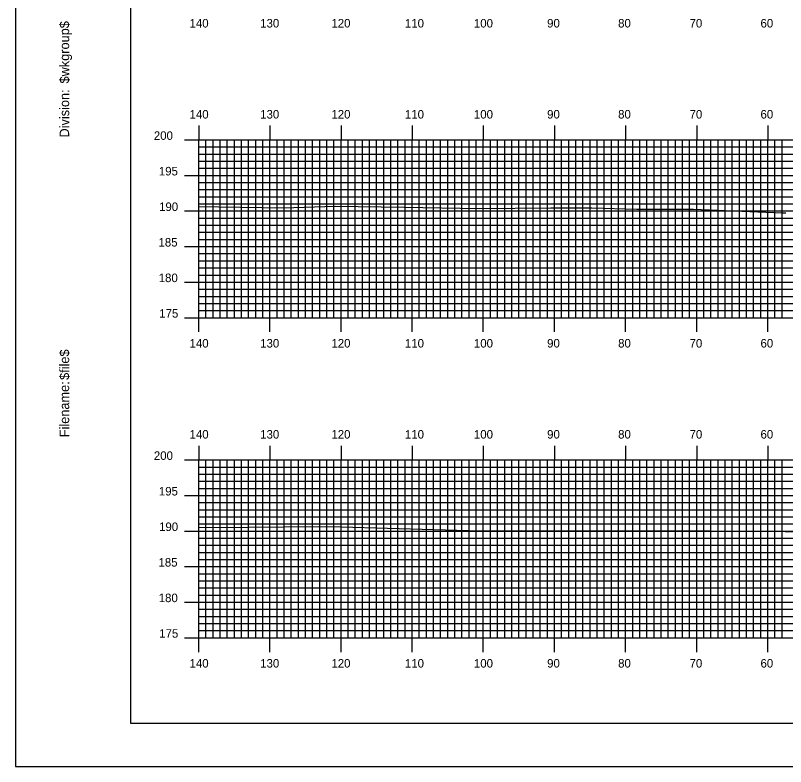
# Model space of a CAD drawing. Extents: x 1797994 to 1798337, y 442591 to 442811.
# Drawn here: x 1797994.2 to 1798102.5, y 442590.5 to 442696.2 of the extents above; entities that cross this region are included whole.
import ezdxf

# ---------------------------------------------------------------- set-up
doc = ezdxf.new("R2010")
doc.units = 0
for name, color, linetype in [('BORDER', 7, 'Continuous'), ('H_V ANNOTATION', 7, 'Continuous'), ('MAJOR', 7, 'Continuous'), ('MINOR', 7, 'Continuous'), ('PLOT BOUNDARY', 7, 'Continuous'), ('S_Roadway_Centerline', 7, 'Continuous')]:
    doc.layers.add(name, color=color, linetype=linetype)

msp = doc.modelspace()

# ---------------------------------------------------------------- linework, layer by layer
at = {"layer": 'BORDER'}
msp.add_lwpolyline([(1798010.36, 442596.67), (1798330.36, 442596.67), (1798330.36, 442806.67), (1798010.36, 442806.67)], close=True, dxfattribs=at)
at = {"layer": 'MAJOR'}
for p, q in [((1798019.96, 442680.67), (1798019.96, 442678.67)), ((1798029.96, 442680.67), (1798029.96, 442678.67)), ((1798039.96, 442680.67), (1798039.96, 442678.67)), ((1798049.96, 442680.67), (1798049.96, 442678.67)), ((1798059.96, 442680.67), (1798059.96, 442678.67)), ((1798069.96, 442680.67), (1798069.96, 442678.67)), ((1798079.96, 442680.67), (1798079.96, 442678.67)), ((1798089.96, 442680.67), (1798089.96, 442678.67)), ((1798099.96, 442680.67), (1798099.96, 442678.67)), ((1798017.95, 442678.67), (1798019.96, 442678.67)), ((1798019.96, 442678.67), (1798299.96, 442678.67)), ((1798019.96, 442653.67), (1798019.96, 442678.67)), ((1798019.96, 442653.67), (1798019.96, 442678.67)), ((1798019.96, 442678.67), (1798299.96, 442678.67)), ((1798029.96, 442653.67), (1798029.96, 442678.67)), ((1798039.96, 442653.67), (1798039.96, 442678.67)), ((1798049.96, 442653.67), (1798049.96, 442678.67)), ((1798059.96, 442653.67), (1798059.96, 442678.67)), ((1798069.96, 442653.67), (1798069.96, 442678.67)), ((1798079.96, 442653.67), (1798079.96, 442678.67)), ((1798089.96, 442653.67), (1798089.96, 442678.67)), ((1798099.96, 442653.67), (1798099.96, 442678.67)), ((1798017.95, 442673.67), (1798019.96, 442673.67)), ((1798019.96, 442673.67), (1798299.96, 442673.67)), ((1798017.95, 442668.67), (1798019.96, 442668.67)), ((1798019.96, 442668.67), (1798299.96, 442668.67)), ((1798017.95, 442663.67), (1798019.96, 442663.67)), ((1798019.96, 442663.67), (1798299.96, 442663.67)), ((1798017.95, 442658.67), (1798019.96, 442658.67)), ((1798019.96, 442658.67), (1798299.96, 442658.67)), ((1798017.95, 442653.67), (1798019.96, 442653.67)), ((1798019.96, 442653.67), (1798299.96, 442653.67)), ((1798019.96, 442653.67), (1798299.96, 442653.67)), ((1798019.96, 442651.66), (1798019.96, 442653.67)), ((1798029.96, 442651.66), (1798029.96, 442653.67)), ((1798039.96, 442651.66), (1798039.96, 442653.67)), ((1798049.96, 442651.66), (1798049.96, 442653.67)), ((1798059.96, 442651.66), (1798059.96, 442653.67)), ((1798069.96, 442651.66), (1798069.96, 442653.67)), ((1798079.96, 442651.66), (1798079.96, 442653.67)), ((1798089.96, 442651.66), (1798089.96, 442653.67)), ((1798099.96, 442651.66), (1798099.96, 442653.67)), ((1798019.96, 442635.67), (1798019.96, 442633.67)), ((1798029.96, 442635.67), (1798029.96, 442633.67)), ((1798039.96, 442635.67), (1798039.96, 442633.67)), ((1798049.96, 442635.67), (1798049.96, 442633.67)), ((1798059.96, 442635.67), (1798059.96, 442633.67)), ((1798069.96, 442635.67), (1798069.96, 442633.67)), ((1798079.96, 442635.67), (1798079.96, 442633.67)), ((1798089.96, 442635.67), (1798089.96, 442633.67)), ((1798099.96, 442635.67), (1798099.96, 442633.67)), ((1798017.95, 442633.67), (1798019.96, 442633.67)), ((1798019.96, 442633.67), (1798299.96, 442633.67)), ((1798019.96, 442608.67), (1798019.96, 442633.67)), ((1798019.96, 442608.67), (1798019.96, 442633.67)), ((1798019.96, 442633.67), (1798299.96, 442633.67)), ((1798029.96, 442608.67), (1798029.96, 442633.67)), ((1798039.96, 442608.67), (1798039.96, 442633.67)), ((1798049.96, 442608.67), (1798049.96, 442633.67)), ((1798059.96, 442608.67), (1798059.96, 442633.67)), ((1798069.96, 442608.67), (1798069.96, 442633.67)), ((1798079.96, 442608.67), (1798079.96, 442633.67)), ((1798089.96, 442608.67), (1798089.96, 442633.67)), ((1798099.96, 442608.67), (1798099.96, 442633.67)), ((1798017.95, 442628.67), (1798019.96, 442628.67)), ((1798019.96, 442628.67), (1798299.96, 442628.67)), ((1798017.95, 442623.67), (1798019.96, 442623.67)), ((1798019.96, 442623.67), (1798299.96, 442623.67)), ((1798017.95, 442618.67), (1798019.96, 442618.67)), ((1798019.96, 442618.67), (1798299.96, 442618.67)), ((1798017.95, 442613.67), (1798019.96, 442613.67)), ((1798019.96, 442613.67), (1798299.96, 442613.67)), ((1798017.95, 442608.67), (1798019.96, 442608.67)), ((1798019.96, 442608.67), (1798299.96, 442608.67)), ((1798019.96, 442608.67), (1798299.96, 442608.67)), ((1798019.96, 442606.66), (1798019.96, 442608.67)), ((1798029.96, 442606.66), (1798029.96, 442608.67)), ((1798039.96, 442606.66), (1798039.96, 442608.67)), ((1798049.96, 442606.66), (1798049.96, 442608.67)), ((1798059.96, 442606.66), (1798059.96, 442608.67)), ((1798069.96, 442606.66), (1798069.96, 442608.67)), ((1798079.96, 442606.66), (1798079.96, 442608.67)), ((1798089.96, 442606.66), (1798089.96, 442608.67)), ((1798099.96, 442606.66), (1798099.96, 442608.67))]:
    msp.add_line(p, q, dxfattribs=at)
at = {"layer": 'MINOR'}
for p, q in [((1798020.96, 442653.67), (1798020.96, 442678.67)), ((1798021.96, 442653.67), (1798021.96, 442678.67)), ((1798022.96, 442653.67), (1798022.96, 442678.67)), ((1798023.96, 442653.67), (1798023.96, 442678.67)), ((1798024.96, 442653.67), (1798024.96, 442678.67)), ((1798025.96, 442653.67), (1798025.96, 442678.67)), ((1798026.96, 442653.67), (1798026.96, 442678.67)), ((1798027.96, 442653.67), (1798027.96, 442678.67)), ((1798028.96, 442653.67), (1798028.96, 442678.67)), ((1798030.96, 442653.67), (1798030.96, 442678.67)), ((1798031.96, 442653.67), (1798031.96, 442678.67)), ((1798032.96, 442653.67), (1798032.96, 442678.67)), ((1798033.96, 442653.67), (1798033.96, 442678.67)), ((1798034.96, 442653.67), (1798034.96, 442678.67)), ((1798035.96, 442653.67), (1798035.96, 442678.67)), ((1798036.96, 442653.67), (1798036.96, 442678.67)), ((1798037.96, 442653.67), (1798037.96, 442678.67)), ((1798038.96, 442653.67), (1798038.96, 442678.67)), ((1798040.96, 442653.67), (1798040.96, 442678.67)), ((1798041.96, 442653.67), (1798041.96, 442678.67)), ((1798042.96, 442653.67), (1798042.96, 442678.67)), ((1798043.96, 442653.67), (1798043.96, 442678.67)), ((1798044.96, 442653.67), (1798044.96, 442678.67)), ((1798045.96, 442653.67), (1798045.96, 442678.67)), ((1798046.96, 442653.67), (1798046.96, 442678.67)), ((1798047.96, 442653.67), (1798047.96, 442678.67)), ((1798048.96, 442653.67), (1798048.96, 442678.67)), ((1798050.96, 442653.67), (1798050.96, 442678.67)), ((1798051.96, 442653.67), (1798051.96, 442678.67)), ((1798052.96, 442653.67), (1798052.96, 442678.67)), ((1798053.96, 442653.67), (1798053.96, 442678.67)), ((1798054.96, 442653.67), (1798054.96, 442678.67)), ((1798055.96, 442653.67), (1798055.96, 442678.67)), ((1798056.96, 442653.67), (1798056.96, 442678.67)), ((1798057.96, 442653.67), (1798057.96, 442678.67)), ((1798058.96, 442653.67), (1798058.96, 442678.67)), ((1798060.96, 442653.67), (1798060.96, 442678.67)), ((1798061.96, 442653.67), (1798061.96, 442678.67)), ((1798062.96, 442653.67), (1798062.96, 442678.67)), ((1798063.96, 442653.67), (1798063.96, 442678.67)), ((1798064.96, 442653.67), (1798064.96, 442678.67)), ((1798065.96, 442653.67), (1798065.96, 442678.67)), ((1798066.96, 442653.67), (1798066.96, 442678.67)), ((1798067.96, 442653.67), (1798067.96, 442678.67)), ((1798068.96, 442653.67), (1798068.96, 442678.67)), ((1798070.96, 442653.67), (1798070.96, 442678.67)), ((1798071.96, 442653.67), (1798071.96, 442678.67)), ((1798072.96, 442653.67), (1798072.96, 442678.67)), ((1798073.96, 442653.67), (1798073.96, 442678.67)), ((1798074.96, 442653.67), (1798074.96, 442678.67)), ((1798075.96, 442653.67), (1798075.96, 442678.67)), ((1798076.96, 442653.67), (1798076.96, 442678.67)), ((1798077.96, 442653.67), (1798077.96, 442678.67)), ((1798078.96, 442653.67), (1798078.96, 442678.67)), ((1798080.96, 442653.67), (1798080.96, 442678.67)), ((1798081.96, 442653.67), (1798081.96, 442678.67)), ((1798082.96, 442653.67), (1798082.96, 442678.67)), ((1798083.96, 442653.67), (1798083.96, 442678.67)), ((1798084.96, 442653.67), (1798084.96, 442678.67)), ((1798085.96, 442653.67), (1798085.96, 442678.67)), ((1798086.96, 442653.67), (1798086.96, 442678.67)), ((1798087.96, 442653.67), (1798087.96, 442678.67)), ((1798088.96, 442653.67), (1798088.96, 442678.67)), ((1798090.96, 442653.67), (1798090.96, 442678.67)), ((1798091.96, 442653.67), (1798091.96, 442678.67)), ((1798092.96, 442653.67), (1798092.96, 442678.67)), ((1798093.96, 442653.67), (1798093.96, 442678.67)), ((1798094.96, 442653.67), (1798094.96, 442678.67)), ((1798095.96, 442653.67), (1798095.96, 442678.67)), ((1798096.96, 442653.67), (1798096.96, 442678.67)), ((1798097.96, 442653.67), (1798097.96, 442678.67)), ((1798098.96, 442653.67), (1798098.96, 442678.67)), ((1798100.96, 442653.67), (1798100.96, 442678.67)), ((1798101.96, 442653.67), (1798101.96, 442678.67)), ((1798019.96, 442677.67), (1798299.96, 442677.67)), ((1798019.96, 442677.67), (1798021.96, 442677.67)), ((1798019.96, 442676.67), (1798299.96, 442676.67)), ((1798019.96, 442676.67), (1798021.96, 442676.67)), ((1798019.96, 442675.67), (1798299.96, 442675.67)), ((1798019.96, 442675.67), (1798021.96, 442675.67)), ((1798019.96, 442674.67), (1798299.96, 442674.67)), ((1798019.96, 442674.67), (1798021.96, 442674.67)), ((1798019.96, 442672.67), (1798299.96, 442672.67)), ((1798019.96, 442672.67), (1798021.96, 442672.67)), ((1798019.96, 442671.67), (1798299.96, 442671.67)), ((1798019.96, 442671.67), (1798021.96, 442671.67)), ((1798019.96, 442670.67), (1798299.96, 442670.67)), ((1798019.96, 442670.67), (1798021.96, 442670.67)), ((1798019.96, 442669.67), (1798299.96, 442669.67)), ((1798019.96, 442669.67), (1798021.96, 442669.67)), ((1798019.96, 442667.67), (1798299.96, 442667.67)), ((1798019.96, 442667.67), (1798021.96, 442667.67)), ((1798019.96, 442666.67), (1798299.96, 442666.67)), ((1798019.96, 442666.67), (1798021.96, 442666.67)), ((1798019.96, 442665.67), (1798299.96, 442665.67)), ((1798019.96, 442665.67), (1798021.96, 442665.67)), ((1798019.96, 442664.67), (1798299.96, 442664.67)), ((1798019.96, 442664.67), (1798021.96, 442664.67)), ((1798019.96, 442662.67), (1798299.96, 442662.67)), ((1798019.96, 442662.67), (1798021.96, 442662.67)), ((1798019.96, 442661.67), (1798299.96, 442661.67)), ((1798019.96, 442661.67), (1798021.96, 442661.67)), ((1798019.96, 442660.67), (1798299.96, 442660.67)), ((1798019.96, 442660.67), (1798021.96, 442660.67)), ((1798019.96, 442659.67), (1798299.96, 442659.67)), ((1798019.96, 442659.67), (1798021.96, 442659.67)), ((1798019.96, 442657.67), (1798299.96, 442657.67)), ((1798019.96, 442657.67), (1798021.96, 442657.67)), ((1798019.96, 442656.67), (1798299.96, 442656.67)), ((1798019.96, 442656.67), (1798021.96, 442656.67)), ((1798019.96, 442655.67), (1798299.96, 442655.67)), ((1798019.96, 442655.67), (1798021.96, 442655.67)), ((1798019.96, 442654.67), (1798299.96, 442654.67)), ((1798019.96, 442654.67), (1798021.96, 442654.67)), ((1798020.96, 442608.67), (1798020.96, 442633.67)), ((1798021.96, 442608.67), (1798021.96, 442633.67)), ((1798022.96, 442608.67), (1798022.96, 442633.67)), ((1798023.96, 442608.67), (1798023.96, 442633.67)), ((1798024.96, 442608.67), (1798024.96, 442633.67)), ((1798025.96, 442608.67), (1798025.96, 442633.67)), ((1798026.96, 442608.67), (1798026.96, 442633.67)), ((1798027.96, 442608.67), (1798027.96, 442633.67)), ((1798028.96, 442608.67), (1798028.96, 442633.67)), ((1798030.96, 442608.67), (1798030.96, 442633.67)), ((1798031.96, 442608.67), (1798031.96, 442633.67)), ((1798032.96, 442608.67), (1798032.96, 442633.67)), ((1798033.96, 442608.67), (1798033.96, 442633.67)), ((1798034.96, 442608.67), (1798034.96, 442633.67)), ((1798035.96, 442608.67), (1798035.96, 442633.67)), ((1798036.96, 442608.67), (1798036.96, 442633.67)), ((1798037.96, 442608.67), (1798037.96, 442633.67)), ((1798038.96, 442608.67), (1798038.96, 442633.67)), ((1798040.96, 442608.67), (1798040.96, 442633.67)), ((1798041.96, 442608.67), (1798041.96, 442633.67)), ((1798042.96, 442608.67), (1798042.96, 442633.67)), ((1798043.96, 442608.67), (1798043.96, 442633.67)), ((1798044.96, 442608.67), (1798044.96, 442633.67)), ((1798045.96, 442608.67), (1798045.96, 442633.67)), ((1798046.96, 442608.67), (1798046.96, 442633.67)), ((1798047.96, 442608.67), (1798047.96, 442633.67)), ((1798048.96, 442608.67), (1798048.96, 442633.67)), ((1798050.96, 442608.67), (1798050.96, 442633.67)), ((1798051.96, 442608.67), (1798051.96, 442633.67)), ((1798052.96, 442608.67), (1798052.96, 442633.67)), ((1798053.96, 442608.67), (1798053.96, 442633.67)), ((1798054.96, 442608.67), (1798054.96, 442633.67)), ((1798055.96, 442608.67), (1798055.96, 442633.67)), ((1798056.96, 442608.67), (1798056.96, 442633.67)), ((1798057.96, 442608.67), (1798057.96, 442633.67)), ((1798058.96, 442608.67), (1798058.96, 442633.67)), ((1798060.96, 442608.67), (1798060.96, 442633.67)), ((1798061.96, 442608.67), (1798061.96, 442633.67)), ((1798062.96, 442608.67), (1798062.96, 442633.67)), ((1798063.96, 442608.67), (1798063.96, 442633.67)), ((1798064.96, 442608.67), (1798064.96, 442633.67)), ((1798065.96, 442608.67), (1798065.96, 442633.67)), ((1798066.96, 442608.67), (1798066.96, 442633.67)), ((1798067.96, 442608.67), (1798067.96, 442633.67)), ((1798068.96, 442608.67), (1798068.96, 442633.67)), ((1798070.96, 442608.67), (1798070.96, 442633.67)), ((1798071.96, 442608.67), (1798071.96, 442633.67)), ((1798072.96, 442608.67), (1798072.96, 442633.67)), ((1798073.96, 442608.67), (1798073.96, 442633.67)), ((1798074.96, 442608.67), (1798074.96, 442633.67)), ((1798075.96, 442608.67), (1798075.96, 442633.67)), ((1798076.96, 442608.67), (1798076.96, 442633.67)), ((1798077.96, 442608.67), (1798077.96, 442633.67)), ((1798078.96, 442608.67), (1798078.96, 442633.67)), ((1798080.96, 442608.67), (1798080.96, 442633.67)), ((1798081.96, 442608.67), (1798081.96, 442633.67)), ((1798082.96, 442608.67), (1798082.96, 442633.67)), ((1798083.96, 442608.67), (1798083.96, 442633.67)), ((1798084.96, 442608.67), (1798084.96, 442633.67)), ((1798085.96, 442608.67), (1798085.96, 442633.67)), ((1798086.96, 442608.67), (1798086.96, 442633.67)), ((1798087.96, 442608.67), (1798087.96, 442633.67)), ((1798088.96, 442608.67), (1798088.96, 442633.67)), ((1798090.96, 442608.67), (1798090.96, 442633.67)), ((1798091.96, 442608.67), (1798091.96, 442633.67)), ((1798092.96, 442608.67), (1798092.96, 442633.67)), ((1798093.96, 442608.67), (1798093.96, 442633.67)), ((1798094.96, 442608.67), (1798094.96, 442633.67)), ((1798095.96, 442608.67), (1798095.96, 442633.67)), ((1798096.96, 442608.67), (1798096.96, 442633.67)), ((1798097.96, 442608.67), (1798097.96, 442633.67)), ((1798098.96, 442608.67), (1798098.96, 442633.67)), ((1798100.96, 442608.67), (1798100.96, 442633.67)), ((1798101.96, 442608.67), (1798101.96, 442633.67)), ((1798019.96, 442632.67), (1798299.96, 442632.67)), ((1798019.96, 442632.67), (1798021.96, 442632.67)), ((1798019.96, 442631.67), (1798299.96, 442631.67)), ((1798019.96, 442631.67), (1798021.96, 442631.67)), ((1798019.96, 442630.67), (1798299.96, 442630.67)), ((1798019.96, 442630.67), (1798021.96, 442630.67)), ((1798019.96, 442629.67), (1798299.96, 442629.67)), ((1798019.96, 442629.67), (1798021.96, 442629.67)), ((1798019.96, 442627.67), (1798299.96, 442627.67)), ((1798019.96, 442627.67), (1798021.96, 442627.67)), ((1798019.96, 442626.67), (1798299.96, 442626.67)), ((1798019.96, 442626.67), (1798021.96, 442626.67)), ((1798019.96, 442625.67), (1798299.96, 442625.67)), ((1798019.96, 442625.67), (1798021.96, 442625.67)), ((1798019.96, 442624.67), (1798299.96, 442624.67)), ((1798019.96, 442624.67), (1798021.96, 442624.67)), ((1798019.96, 442622.67), (1798299.96, 442622.67)), ((1798019.96, 442622.67), (1798021.96, 442622.67)), ((1798019.96, 442621.67), (1798299.96, 442621.67)), ((1798019.96, 442621.67), (1798021.96, 442621.67)), ((1798019.96, 442620.67), (1798299.96, 442620.67)), ((1798019.96, 442620.67), (1798021.96, 442620.67)), ((1798019.96, 442619.67), (1798299.96, 442619.67)), ((1798019.96, 442619.67), (1798021.96, 442619.67)), ((1798019.96, 442617.67), (1798299.96, 442617.67)), ((1798019.96, 442617.67), (1798021.96, 442617.67)), ((1798019.96, 442616.67), (1798299.96, 442616.67)), ((1798019.96, 442616.67), (1798021.96, 442616.67)), ((1798019.96, 442615.67), (1798299.96, 442615.67)), ((1798019.96, 442615.67), (1798021.96, 442615.67)), ((1798019.96, 442614.67), (1798299.96, 442614.67)), ((1798019.96, 442614.67), (1798021.96, 442614.67)), ((1798019.96, 442612.67), (1798299.96, 442612.67)), ((1798019.96, 442612.67), (1798021.96, 442612.67)), ((1798019.96, 442611.67), (1798299.96, 442611.67)), ((1798019.96, 442611.67), (1798021.96, 442611.67)), ((1798019.96, 442610.67), (1798299.96, 442610.67)), ((1798019.96, 442610.67), (1798021.96, 442610.67)), ((1798019.96, 442609.67), (1798299.96, 442609.67)), ((1798019.96, 442609.67), (1798021.96, 442609.67))]:
    msp.add_line(p, q, dxfattribs=at)
at = {"layer": 'PLOT BOUNDARY'}
msp.add_lwpolyline([(1797994.17, 442590.55), (1798334.17, 442590.55), (1798334.17, 442810.55), (1797994.17, 442810.55)], close=True, dxfattribs=at)
at = {"layer": 'S_Roadway_Centerline'}
for points in [[(1798019.96, 442669.28), (1798022.75, 442669.27), (1798031.88, 442669.13), (1798039.14, 442669.35), (1798048.85, 442669.2), (1798059.39, 442669.03), (1798069.46, 442669.1), (1798075.23, 442669.11), (1798081.52, 442668.93), (1798089.51, 442668.94), (1798101.92, 442668.42), (1798102.25, 442668.41), (1798102.51, 442668.41)], [(1798019.96, 442624.18), (1798026.96, 442624.23), (1798036.73, 442624.33), (1798039.99, 442624.27), (1798059.51, 442623.72), (1798061.88, 442623.71), (1798065.3, 442623.74), (1798080.87, 442623.7), (1798092, 442623.71), (1798102.39, 442623.6), (1798118.19, 442623.52), (1798120.17, 442623.54), (1798121.59, 442623.48), (1798143.17, 442622.99), (1798143.68, 442622.99), (1798144.17, 442623), (1798155.33, 442623.07), (1798165.69, 442622.78), (1798179.35, 442622.67), (1798186.61, 442622.56), (1798195.7, 442622.49), (1798202.28, 442622.51), (1798207.69, 442622.6), (1798213.43, 442622.63)]]:
    msp.add_lwpolyline(points, dxfattribs=at)

# ---------------------------------------------------------------- texts
at = {"layer": 'BORDER'}
for s, p in [('$wkgroup$', (1798001.73, 442686.6)), ('Division:', (1798001.73, 442679)), ('$file$', (1798001.73, 442644.92)), ('Filename:', (1798001.73, 442636.86))]:
    msp.add_text(s, height=1.339, rotation=90, dxfattribs=at).set_placement(p)
at = {"layer": 'H_V ANNOTATION'}
for s, p in [('140', (1798018.66, 442694.47)), ('130', (1798028.59, 442694.47)), ('120', (1798038.6, 442694.47)), ('110', (1798048.94, 442694.47)), ('100', (1798058.64, 442694.47)), ('90', (1798068.93, 442694.47)), ('80', (1798078.91, 442694.47)), ('70', (1798088.96, 442694.47)), ('60', (1798098.93, 442694.47)), ('140', (1798018.66, 442681.67)), ('130', (1798028.59, 442681.67)), ('120', (1798038.6, 442681.67)), ('110', (1798048.94, 442681.67)), ('100', (1798058.64, 442681.67)), ('90', (1798068.93, 442681.67)), ('80', (1798078.91, 442681.67)), ('70', (1798088.96, 442681.67)), ('60', (1798098.93, 442681.67)), ('200', (1798013.64, 442678.67)), ('195', (1798014.34, 442673.67)), ('190', (1798014.37, 442668.67)), ('185', (1798014.29, 442663.67)), ('180', (1798014.32, 442658.67)), ('175', (1798014.4, 442653.67)), ('140', (1798018.66, 442649.47)), ('130', (1798028.59, 442649.47)), ('120', (1798038.6, 442649.47)), ('110', (1798048.94, 442649.47)), ('100', (1798058.64, 442649.47)), ('90', (1798068.93, 442649.47)), ('80', (1798078.91, 442649.47)), ('70', (1798088.96, 442649.47)), ('60', (1798098.93, 442649.47)), ('140', (1798018.66, 442636.67)), ('130', (1798028.59, 442636.67)), ('120', (1798038.6, 442636.67)), ('110', (1798048.94, 442636.67)), ('100', (1798058.64, 442636.67)), ('90', (1798068.93, 442636.67)), ('80', (1798078.91, 442636.67)), ('70', (1798088.96, 442636.67)), ('60', (1798098.93, 442636.67)), ('200', (1798013.64, 442633.67)), ('195', (1798014.34, 442628.67)), ('190', (1798014.37, 442623.67)), ('185', (1798014.29, 442618.67)), ('180', (1798014.32, 442613.67)), ('175', (1798014.4, 442608.67)), ('140', (1798018.66, 442604.47)), ('130', (1798028.59, 442604.47)), ('120', (1798038.6, 442604.47)), ('110', (1798048.94, 442604.47)), ('100', (1798058.64, 442604.47)), ('90', (1798068.93, 442604.47)), ('80', (1798078.91, 442604.47)), ('70', (1798088.96, 442604.47)), ('60', (1798098.93, 442604.47))]:
    msp.add_text(s, height=1.2, dxfattribs=at).set_placement(p)
at = {"layer": 'MAJOR'}
for p in [(1798019.95, 442653.67), (1798019.95, 442608.67)]:
    msp.add_text('-', height=0.012, dxfattribs=at).set_placement(p)

doc.saveas('drawing.dxf')
